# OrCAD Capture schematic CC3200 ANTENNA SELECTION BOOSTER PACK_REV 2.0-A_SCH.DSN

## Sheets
1 PAGE2: size B
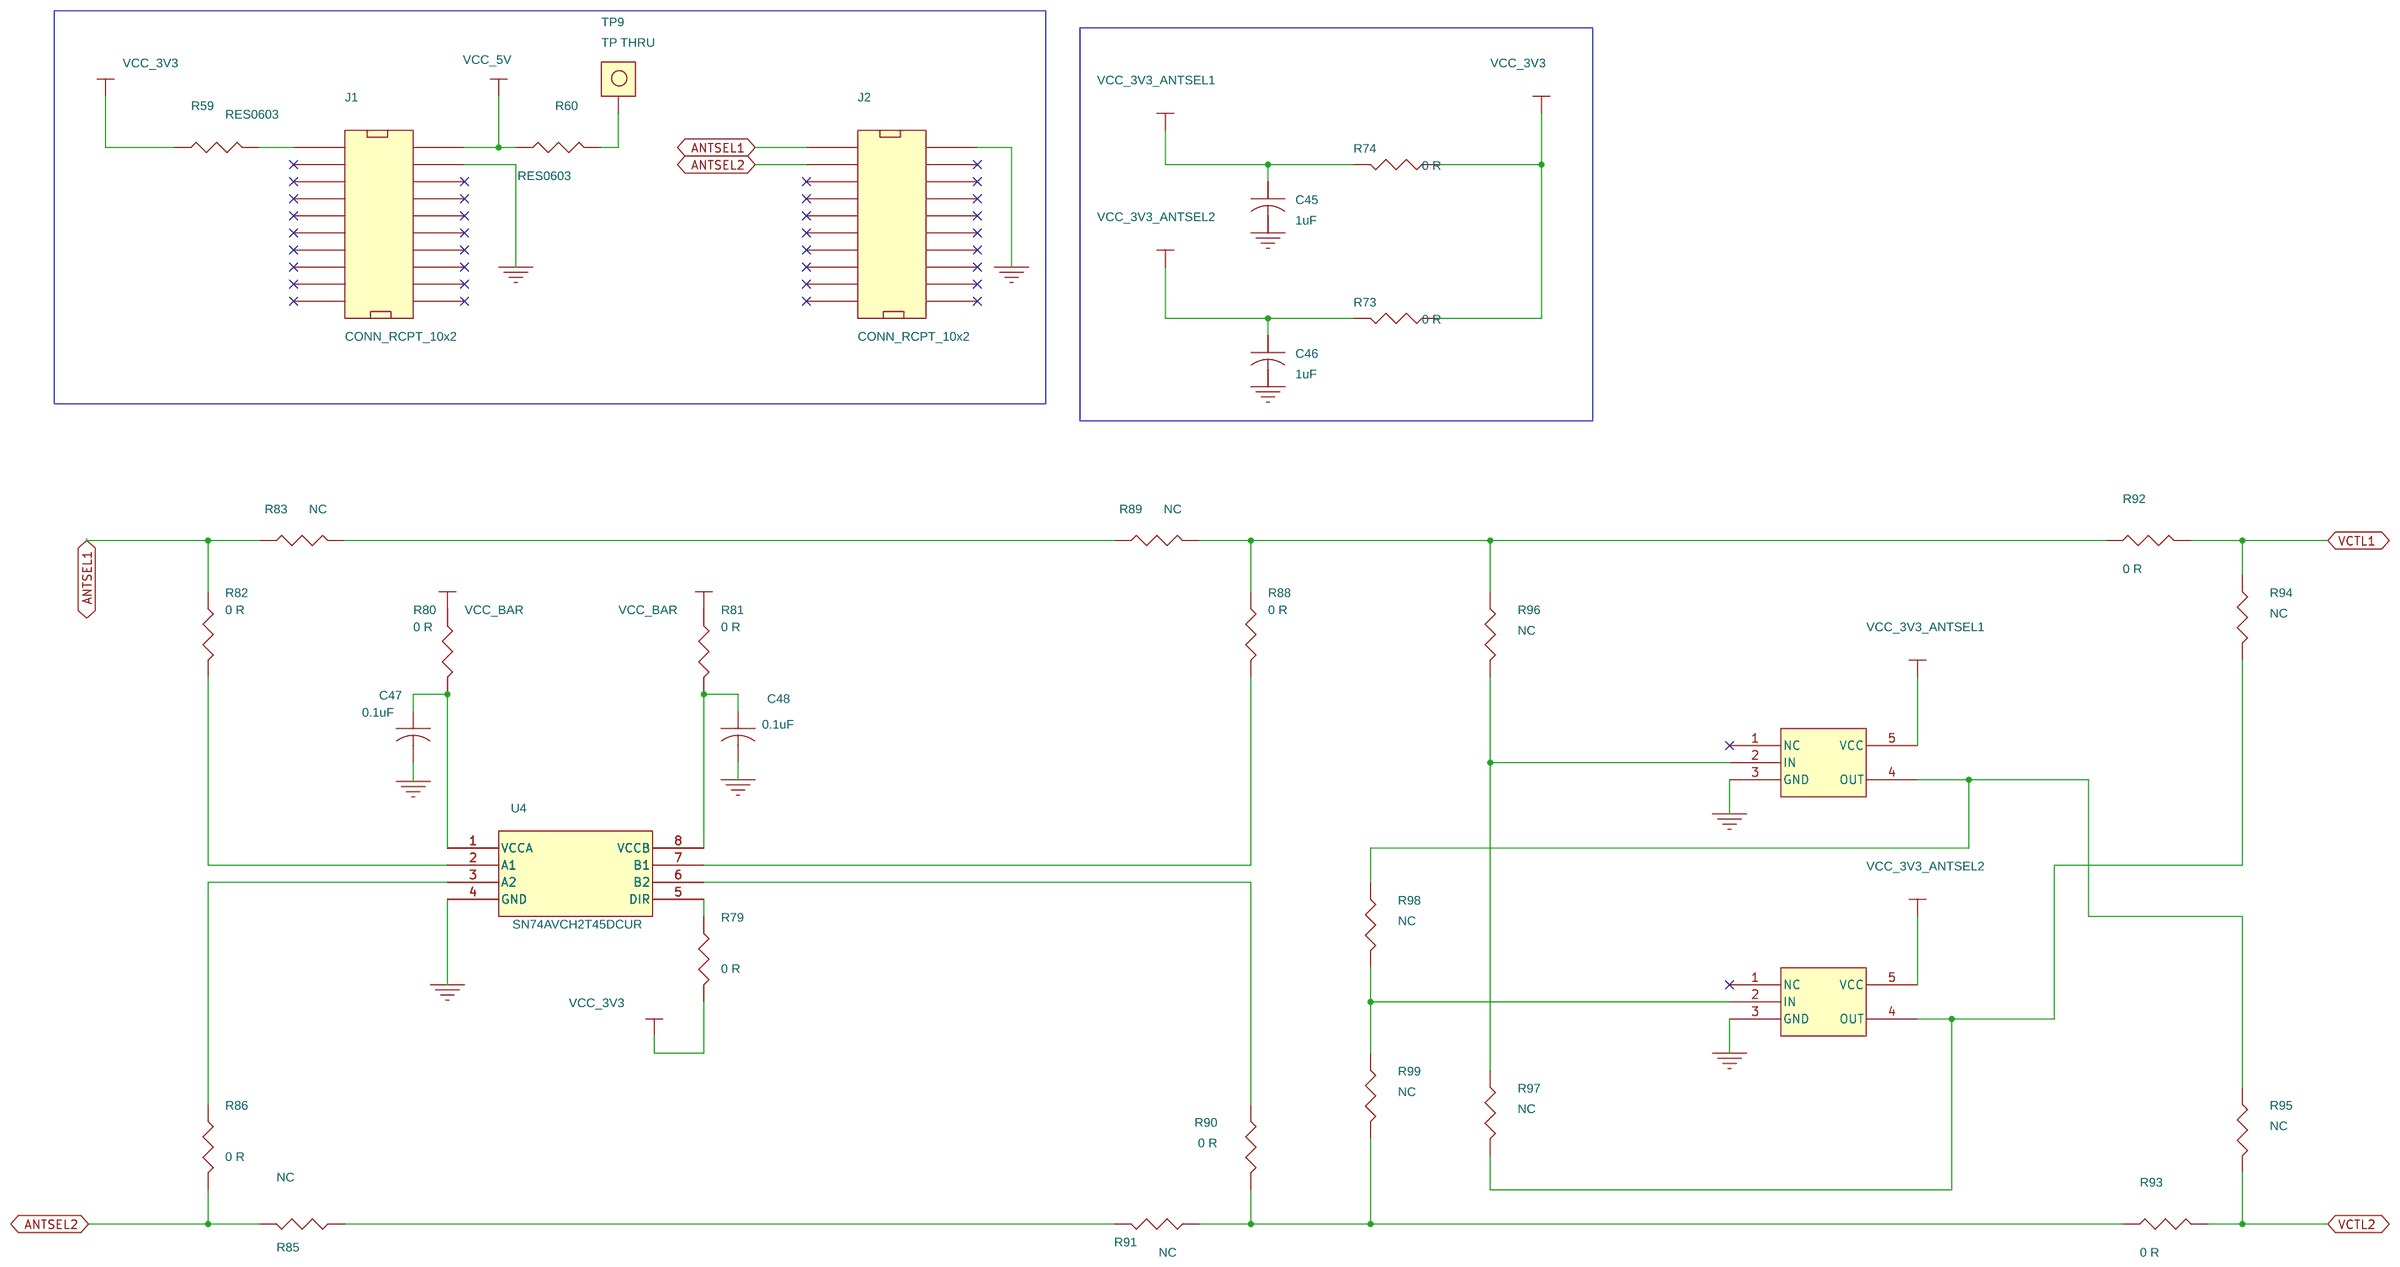
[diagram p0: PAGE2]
2 PAGE1: size C
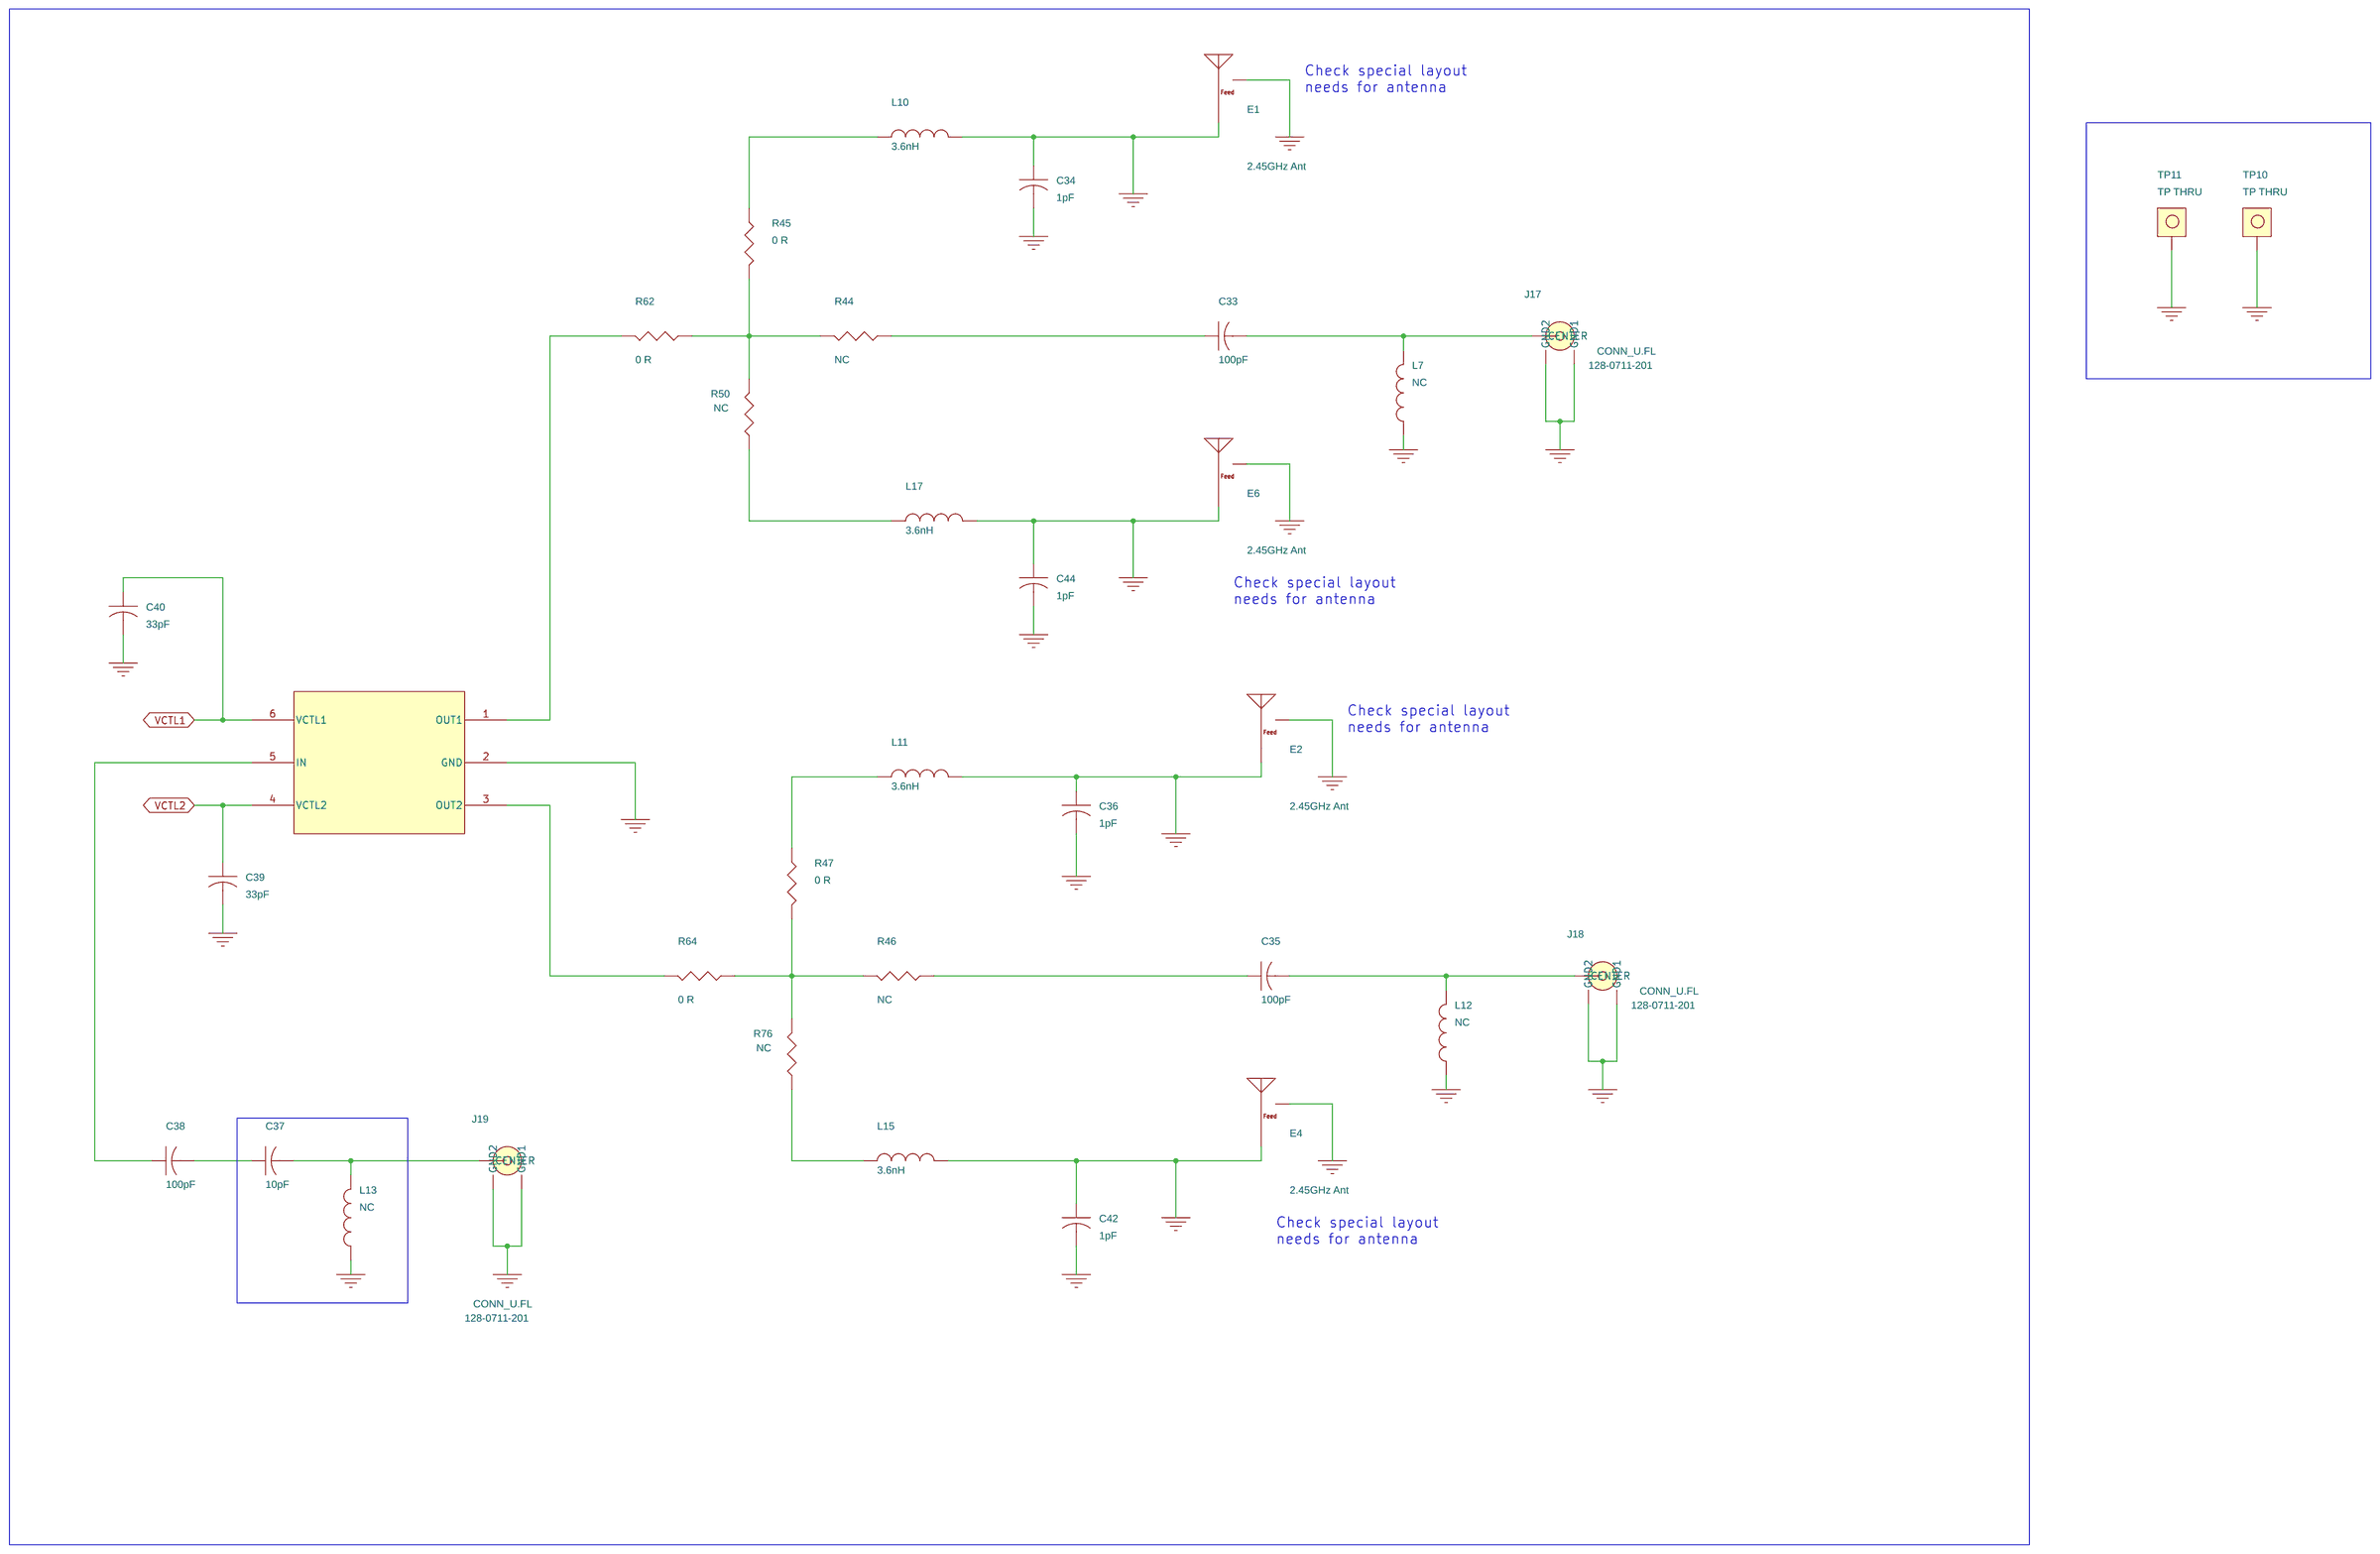
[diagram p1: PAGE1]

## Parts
sheet PAGE1
C33  100pF  [CC0402]
C34  1pF  [CC0402]
C35  100pF  [CC0402]
C36  1pF  [CC0402]
C37  10pF  [CC0402]
C38  100pF  [CC0402]
C39  33pF  [CC0402]
C40  33pF  [CC0402]
C42  1pF  [CC0402]
C44  1pF  [CC0402]
E1  2.45GHz Ant  [ANT_AH316M]
E2  2.45GHz Ant  [ANT_AH316M]
E4  2.45GHz Ant  [ANT_AH316M]
E6  2.45GHz Ant  [ANT_AH316M]
J17  CONN_U.FL  [EMERSON_128-0711-201]
J18  CONN_U.FL  [EMERSON_128-0711-201]
J19  CONN_U.FL  [EMERSON_128-0711-201]
L7  NC  [indc_0402cs]
L10  3.6nH  [indc_0402cs]
L11  3.6nH  [indc_0402cs]
L12  NC  [indc_0402cs]
L13  NC  [indc_0402cs]
L15  3.6nH  [indc_0402cs]
L17  3.6nH  [indc_0402cs]
R44  NC  [rc0402]
R45  0 R  [rc0402]
R46  NC  [rc0402]
R47  0 R  [rc0402]
R50  NC  [rc0402]
R62  0 R  [rc0402]
R64  0 R  [rc0402]
R76  NC  [rc0402]
TP10  TP THRU  [HDR_THVT_1X1_100_M]
TP11  TP THRU  [HDR_THVT_1X1_100_M]
U1  SWITCH  [SW_SKY13351-378LF]
sheet PAGE2
C45  1uF  [CC0402]
C46  1uF  [CC0402]
C47  0.1uF  [CC0402]
C48  0.1uF  [CC0402]
J1  CONN_RCPT_10x2  [HDR_THVT_2X10_100_F]
J2  CONN_RCPT_10x2  [HDR_THVT_2X10_100_F]
R59  RES0603  [RC0603]
R60  RES0603  [RC0603]
R73  0 R  [rc0402]
R74  0 R  [rc0402]
R79  0 R  [rc0402]
R80  0 R  [rc0402]
R81  0 R  [rc0402]
R82  0 R  [rc0402]
R83  NC  [rc0402]
R85  NC  [rc0402]
R86  0 R  [rc0402]
R88  0 R  [rc0402]
R89  NC  [rc0402]
R90  0 R  [rc0402]
R91  NC  [rc0402]
R92  0 R  [rc0402]
R93  0 R  [rc0402]
R94  NC  [rc0402]
R95  NC  [rc0402]
R96  NC  [rc0402]
R97  NC  [rc0402]
R98  NC  [rc0402]
R99  NC  [rc0402]
TP9  TP THRU  [HDR_THVT_1X1_100_M]
U4  SN74AVCH2T45DCUR  [SOP50P310X90-8]
U6  INVERTER  [SOT23-5]
U7  INVERTER  [SOT23-5]

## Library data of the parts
C33-C40 C42 C44-C48 = CAP: CAP CER 10PF 50V NP0 0402; Distributor_Part_Number: 478-5991-2-ND; Mfr_Name: AVX Corporation; Mfr_Part_Number: 04025U100CAT2A; TI_Part_No: TI-CAP-04025U100CAT2A
E1 E2 E4 E6 = CHIP_ANTENNA_2T: ANT BLUETOOTH W-LAN ZIGBEE WIMAX; Distributor_Part_Number: 587-2200-1-ND; Mfr_Name: Taiyo Yuden; Mfr_Part_Number: AH316M245001-T
J17-J19 = CONN_UFL_3P: CONN UMC RCPT STR 50 OHM SMD; Distributor_Part_Number: J983CT-ND; Mfr_Name: Emerson Network Power Connectivity Johnson; Mfr_Part_Number: 128-0711-201; TI_Part_No: TI-COAX-128-0711-201
L7 L10-L13 L15 L17 = INDUCTOR: INDUCTOR HIFREQ 5.6+/-0.3NH 0402; Distributor_Name: Digi-Key; Distributor_Part_Number: 587-1513-1-ND; Manufacturer: Taiyo Yuden; Manufacturer PN: HK10055N6S-T; Mfr_Name: Taiyo Yuden; Mfr_Part_Number: HK10055N6S-T; TI_Part_No: TI-IND-HK10055N6S-T
R44-R47 R50 R62 R64 R73 R74 R76 R79-R83 R85 R86 R88-R99 = RESISTOR: RES 0.0 OHM 1/10W JUMP 0402 SMD; Distributor_Part_Number: P0.0JTR-ND; Mfr_Name: Panasonic Electronic Components; Mfr_Part_Number: ERJ-2GE0R00X; TI_Part_No: TI-Panasonic-ERJ-2GE0R00X
TP9-TP11 = TEST_POINT_THRU: Silk: Vocm
U1 = SWITCH
J1 J2 = CONN_RCPT_10X2: CONN RCPT .100" 20POS DUAL TIN; Distributor_Part_Number: SAM1204-10-ND; Mfr_Name: Samtec; Mfr_Part_Number: SSQ-110-03-T-D; TI_Part_No: TI-CON-SSQ-110-03-T-D; Datasheet: http://www.samtec.com/documents/webfiles/cpdf/SSQ-1XX-XX-XXX-X-XX-XXX-XX-X-MKT.pdf
R59 R60 = RES0603
U4 = SN74AVCH2T45: MANUFACTURER: TEXAS INSTRUMENTS
U6 U7 = INVERTER

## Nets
GND: C34.1 C34.2 C36.1 C36.2 C39.2 C40.2 C42.1 C42.2 C44.1 C44.2 C45.2 C46.2 C47.2 C48.2 E1.1(Feed) E1.2 E2.1(Feed) E2.2 E4.1(Feed) E4.2 E6.1(Feed) E6.2 J1.4 J2.2 J17.2A(GND1) J17.2B(GND2) J18.2A(GND1) J18.2B(GND2) J19.2A(GND1) J19.2B(GND2) L7.1 L10.2 L11.2 L12.1 L13.1 L15.2 L17.2 TP10.1 TP11.1 U1.2(GND) U4.4(GND) U6.3(GND) U7.3(GND)
VCC_3V3: R59.1 R73.2 R74.2 R79.1 R80.2 R81.2
VCC_3V3_ANTSEL1: C45.1 R74.1 U6.5(VCC)
VCC_3V3_ANTSEL2: C46.1 R73.1 U7.5(VCC)
VCC_5V: J1.2 R60.2
ANTSEL1: J2.1 R82.2 R83.2
ANTSEL2: J2.3 R85.2 R86.1
VCTL1: C40.1 R92.1 R94.1 U1.6(VCTL1)
VCTL2: C39.1 R93.1 R95.2 U1.4(VCTL2)
N192262: J1.1 R59.2
N192340: R60.1 TP9.1
N199868: R44.2 R45.1 R50.1 R62.2
N199876: R62.1 U1.1(OUT1)
N199888: R64.1 U1.3(OUT2)
N199912: C38.1 U1.5(IN)
N200476: C37.2 J19.1(CENTER) L13.2
N200512: C37.1 C38.2
N201883: L10.1 R45.2
N202698: C33.2 J17.1(CENTER) L7.2
N202732: C33.1 R44.1
N202976: L17.1 R50.2
N204722: R46.2 R47.1 R64.2 R76.1
N204850: L11.1 R47.2
N204918: C35.2 J18.1(CENTER) L12.2
N204956: C35.1 R46.1
N204984: L15.1 R76.2
N222165: C47.1 R80.1 U4.1(VCCA)
N222453: R88.1 U4.7(B1)
N222461: R90.1 U4.6(B2)
N222517: C48.1 R81.1 U4.8(VCCB)
N223645: R86.2 U4.3(A2)
N225569: R83.1 R89.2
N225701: R88.2 R89.1 R92.2 R96.1
N229561: R82.1 U4.2(A1)
N229933: R85.1 R91.2
N229937: R90.2 R91.1 R93.2 R99.2
N231294: R94.2 R97.2 U7.4(OUT)
N231312: R95.1 R98.1 U6.4(OUT)
N231358: R98.2 R99.1 U7.2(IN)
N231374: R96.2 R97.1 U6.2(IN)
N231796: R79.2 U4.5(DIR)

Not connected (* = marked no-connect by the designer): J1 3* 5* 6* 7* 8* 9* 10* 11* 12* 13* 14* 15* 16* 17* 18* 19* 20*; J2 4* 5* 6* 7* 8* 9* 10* 11* 12* 13* 14* 15* 16* 17* 18* 19* 20*; U6 1(NC)*; U7 1(NC)*

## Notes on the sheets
sheet 2
- Check special layout
  needs for antenna
- Check special layout
  needs for antenna
- Check special layout
  needs for antenna
- Check special layout
  needs for antenna
